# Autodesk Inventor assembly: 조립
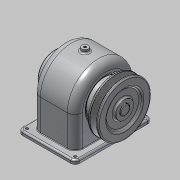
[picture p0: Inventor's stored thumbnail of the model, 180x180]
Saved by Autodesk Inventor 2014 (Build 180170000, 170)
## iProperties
Created: 2016-01
Part Number: 조립
Document SubType Name: Assembly
Designer: user
Mass: 2445.64 g
Surface Area: 1925.88 cm^2
Volume: 534.184 cm^3
Density: 4.57827 g/cm^3
Author: user
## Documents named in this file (12)
- C:\Users\user\Desktop\460106V1006\조립.iam
- C:\Users\user\Desktop\460106V1006\본체.ipt
- C:\Users\user\Desktop\460106V1006\축.ipt
- C:\Users\user\Desktop\460106V1006\키 - 5 x 5 x 18.ipt
- C:\Users\user\Desktop\460106V1006\키 - 6 x 6 x 22.ipt
- C:\Users\user\Desktop\460106V1006\베어링 6203.ipt
- C:\Users\user\Desktop\460106V1006\V-벨트풀리.ipt
- C:\Users\user\Desktop\460106V1006\스퍼기어.ipt
- C:\Users\user\Desktop\460106V1006\뒤커버.ipt
- C:\Users\user\Desktop\460106V1006\앞커버.ipt
- C:\Users\user\Desktop\460106V1006\볼트 M3 x 8.ipt
- C:\Users\user\Desktop\460106V1006\볼트 M3 x 10.ipt
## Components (9 placed, 3 different names)
1. V-벨트풀리:1 — Insert:9, Mate:6
2. ISO 4762 M3 x 8:1 — Insert:10
3. ISO 4762 M3 x 8:2
4. ISO 4762 M3 x 8:3
5. ISO 4762 M3 x 8:4
6. ISO 4762 M3 x 10:1 — Insert:11
7. ISO 4762 M3 x 10:2
8. ISO 4762 M3 x 10:3
9. ISO 4762 M3 x 10:4
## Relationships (4: Insert 3, Mate 1)
- Insert:9: V-벨트풀리:1
- Mate:6: V-벨트풀리:1
- Insert:10: ISO 4762 M3 x 8:1
- Insert:11: ISO 4762 M3 x 10:1
